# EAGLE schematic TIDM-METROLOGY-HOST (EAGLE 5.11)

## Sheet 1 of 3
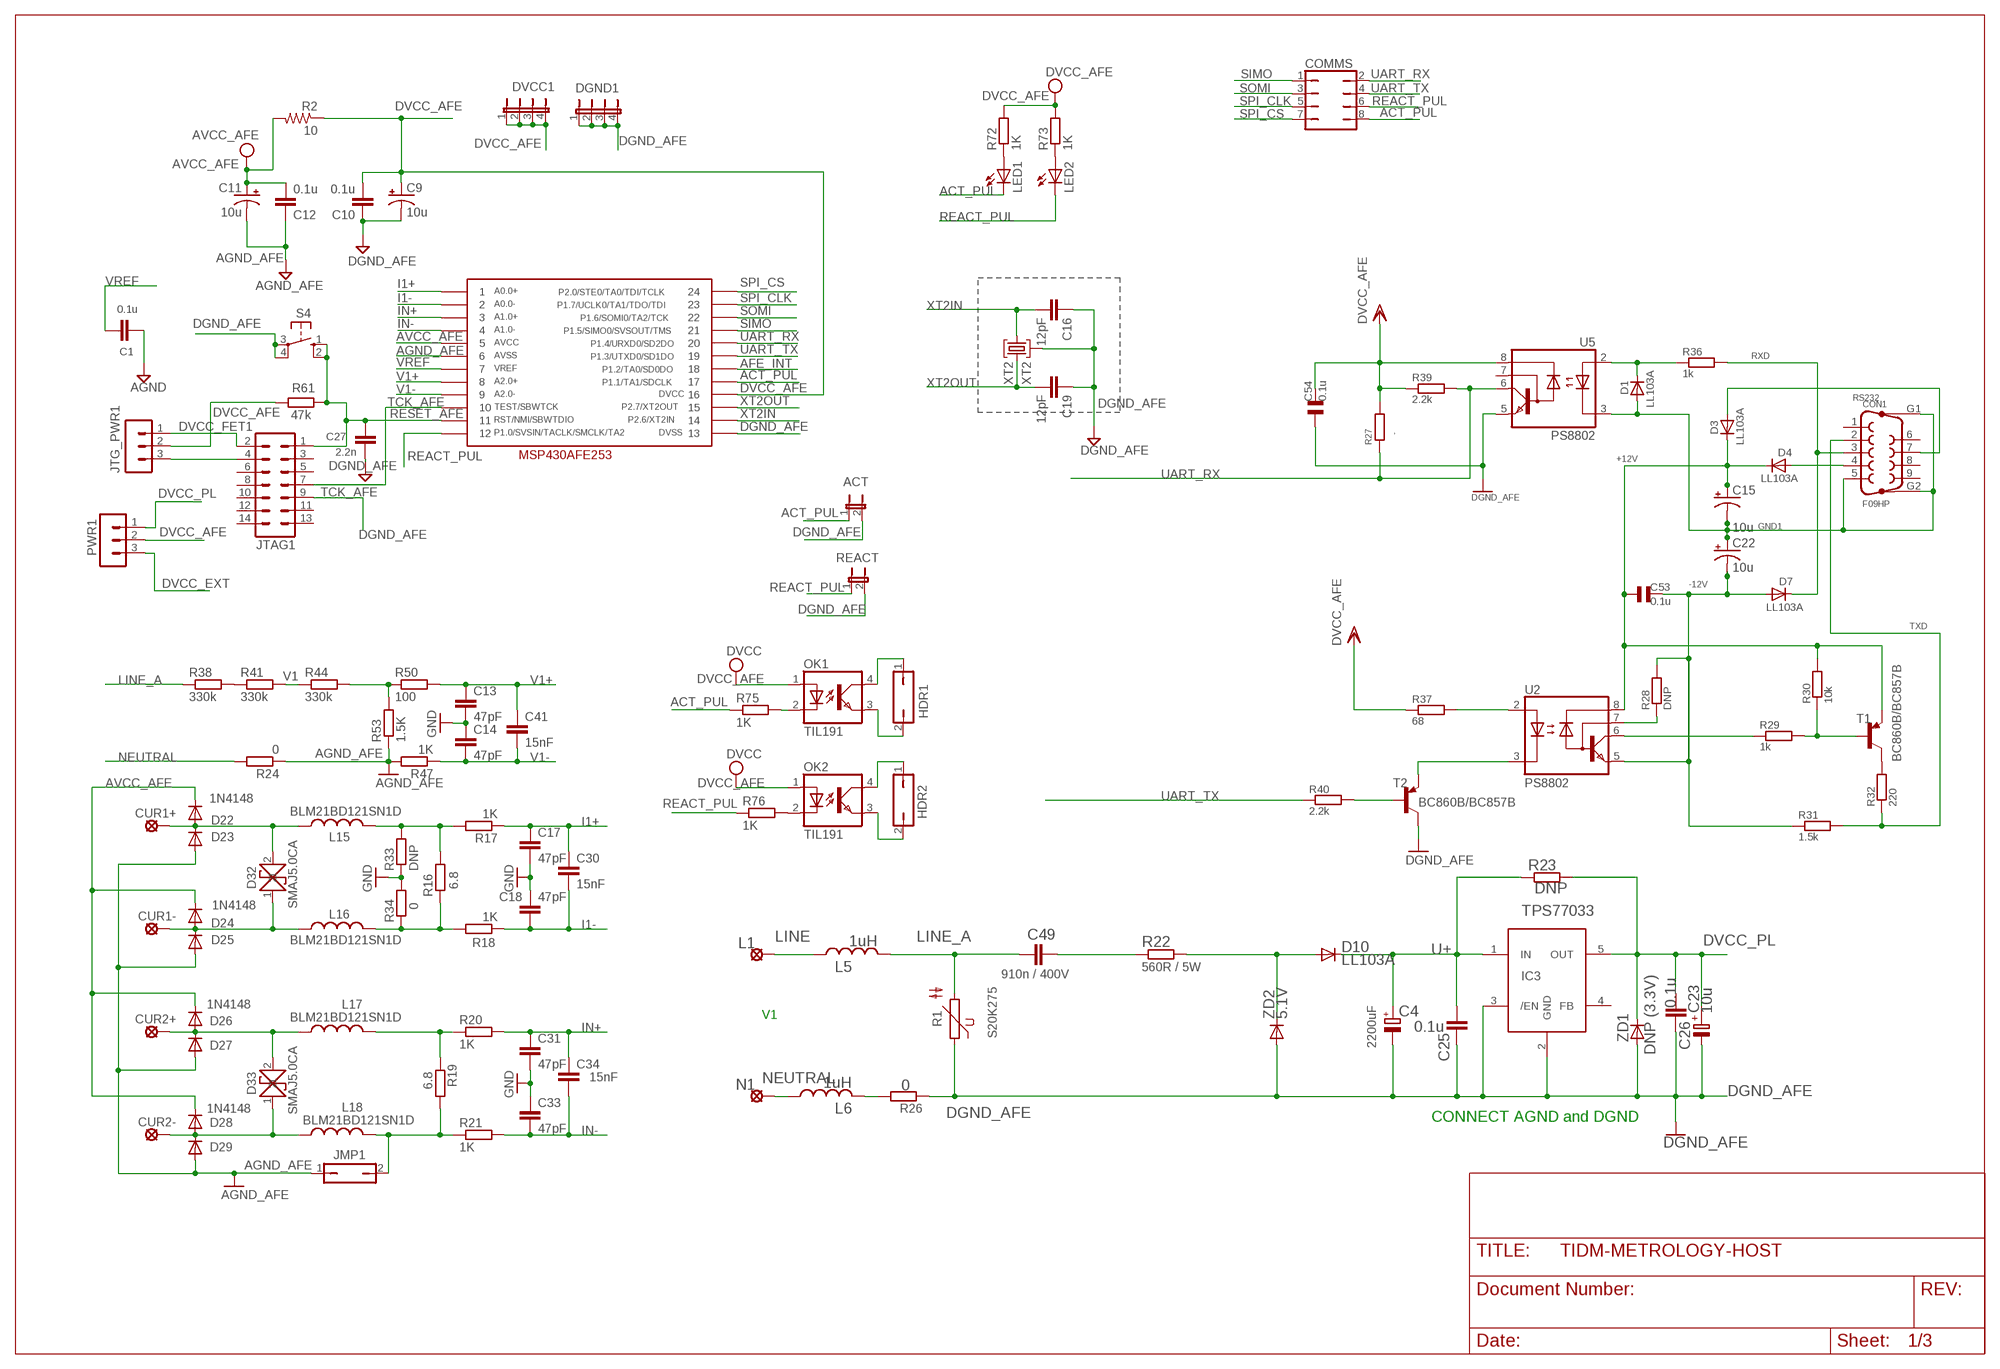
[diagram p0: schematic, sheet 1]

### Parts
ACT  JP1E  [JP1]
C1  0.1u  C-EUC0603  [C0603]
C4  2200uF  CPOL-EUE5-13  [E5-13]
C9  10u  CPOL-USCT3216  [CT3216]
C10  0.1u  C-EUC0603  [C0603]
C11  10u  CPOL-USCT3216  [CT3216]
C12  0.1u  C-EUC0603  [C0603]
C13  47pF  C-EUC0603  [C0603]
C14  47pF  C-EUC0603  [C0603]
C15  10u  CPOL-USCT3216  [CT3216]
C16  12pF  C-EUC0603  [C0603]
C17  47pF  C-EUC0603  [C0603]
C18  47pF  C-EUC0603  [C0603]
C19  12pF  C-EUC0603  [C0603]
C22  10u  CPOL-USCT3216  [CT3216]
C23  10u  ELKO_1210  [1210ELKO]
C25  0.1u  C-EUC0603  [C0603]
C26  0.1u  C-EUC0603  [C0603]
C27  2.2n  C-EUC0603  [C0603]
C30  15nF  C-EUC0603  [C0603]
C31  47pF  C-EUC0603  [C0603]
C33  47pF  C-EUC0603  [C0603]
C34  15nF  C-EUC0603  [C0603]
C41  15nF  C-EUC0603  [C0603]
C49  910n / 400V  C-EU225-062X268  [C225-062X268]
C53  0.1u  CSMD0805  [CSMD0805]
C54  0.1u  CSMD0805  [CSMD0805]
COMMS  JP4Q  [JP4Q]
CON1  F09HP  [F09HP]
CUR1+  LSP10  [LSP10]
CUR1-  LSP10  [LSP10]
CUR2+  LSP10  [LSP10]
CUR2-  LSP10  [LSP10]
D1  LL103A  D  [SOD-80]
D3  LL103A  D  [SOD-80]
D4  LL103A  D  [SOD-80]
D7  LL103A  D  [SOD-80]
D10  LL103A  D  [SOD-80]
D22  1N4148  1N4148SOD80C  [SOD80C]
D23  1N4148  1N4148SOD80C  [SOD80C]
D24  1N4148  1N4148SOD80C  [SOD80C]
D25  1N4148  1N4148SOD80C  [SOD80C]
D26  1N4148  1N4148SOD80C  [SOD80C]
D27  1N4148  1N4148SOD80C  [SOD80C]
D28  1N4148  1N4148SOD80C  [SOD80C]
D29  1N4148  1N4148SOD80C  [SOD80C]
D32  SMAJ5.0CA  SMAJ  [DO-214]
D33  SMAJ5.0CA  SMAJ  [DO-214]
DGND1  JP4E  [JP4]
DVCC1  JP4E  [JP4]
HDR1  JP1Q  [JP1]
HDR2  JP1Q  [JP1]
IC3  TPS77033  TPS77001  [SOT23/5]
JMP1  JP1Q  [JP1]
JTAG1  MA07-2MA07-2JTAG  [MA07-2JTAG]
JTG_PWR1  MA03-1MA03-1  [MA03-1]
L1  LSP10  [LSP10]
L5  1uH  L-US08050805  [0805@1]
L6  1uH  L-US08050805  [0805@1]
L15  BLM21BD121SN1D  L-USL2012C  [L2012C]
L16  BLM21BD121SN1D  L-USL2012C  [L2012C]
L17  BLM21BD121SN1D  L-USL2012C  [L2012C]
L18  BLM21BD121SN1D  L-USL2012C  [L2012C]
LED1  LED3MM  [LED3MM]
LED2  LED3MM  [LED3MM]
N1  LSP10  [LSP10]
OK1  TIL191  [DIL04]
OK2  TIL191  [DIL04]
PWR1  MA03-1MA03-1  [MA03-1]
R1  S20K275  [S20K275]
R2  10  R-US_R0603  [R0603]
R16  6.8  R-EU_R0603  [R0603]
R17  1K  R-EU_R0603  [R0603]
R18  1K  R-EU_R0603  [R0603]
R19  6.8  R-EU_R0603  [R0603]
R20  1K  R-EU_R0603  [R0603]
R21  1K  R-EU_R0603  [R0603]
R22  560R / 5W  R-EU_0817/7V  [P0817V@1]
R23  DNP  R_0805  [0805]
R24  0  R-EU_R0603  [R0603]
R26  0  R-EU_R0603  [R0603]
R27  -  0204/5  [0805]
R28  DNP  R_0805  [0805]
R29  1k  R_0805  [0805]
R30  10k  R_0805  [0805]
R31  1.5k  R_0805  [0805]
R32  220  R_0805  [0805]
R33  DNP  R-EU_R0603  [R0603]
R34  0  R-EU_R0603  [R0603]
R36  1k  R_0805  [0805]
R37  68  R_0805  [0805]
R38  330k  R-EU_R0603  [R0603]
R39  2.2k  R_0805  [0805]
R40  2.2k  R_0805  [0805]
R41  330k  R-EU_R0603  [R0603]
R44  330k  R-EU_R0603  [R0603]
R47  1K  R-EU_R0603  [R0603]
R50  100  R-EU_R0603  [R0603]
R53  1.5K  R-EU_R0603  [R0603]
R61  47k  R-EU_R0603  [R0603]
R72  1K  R-EU_R0603  [R0603]
R73  1K  R-EU_R0603  [R0603]
R75  1K  R-EU_R0603  [R0603]
R76  1K  R-EU_R0603  [R0603]
REACT  JP1E  [JP1]
S4  10-XX  [B3F-10XX]
T1  BC860B/BC857B  BC857ASMD  [SOT23-BEC]
T2  BC860B/BC857B  BC857ASMD  [SOT23-BEC]
U2  PS8802  PS8802SO08  [SO08]
U5  PS8802  PS8802SO08  [SO08]
U$1  MSP430AFE_24TSSOP  [MSP430AFE_24TSSOP]
XT2  XT2  X905  [X905]
ZD1  DNP (3.3V)  D  [SOD-80]
ZD2  5.1V  D  [SOD-80]

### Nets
+12V: C15.+ C53.1 D3.2(K) D4.2(K) R30.2 T1.E U2.8(VCC)
+12V1: CON1.7 D3.1(A)
+12V3: CON1.4 D4.1(A)
-12V: C22.- C53.2 D7.1(A) R28.2 R31.1 U2.5(GND)
ACT_PUL: ACT.1 COMMS.8 LED1.K(C) R75.1 U$1.P$17
AFE_INT: U$1.P$18 ; also sheet 2
AGND_AFE: C1.1 C11.- C12.1 C13.2 C14.1 C17.2 C18.1 C31.2 C33.1 D23.A D25.A D27.A D29.A JMP1.1 R24.1 R33.1 R34.2 R47.2 R53.1 U$1.P$6 ; supply symbol labelled GND, AGND
AVCC_AFE: C11.+ C12.2 D22.C D24.C D26.C D28.C R2.2 U$1.P$5
DGND_AFE: ACT.2 C4.- C9.- C10.1 C16.1 C19.1 C23.- C25.1 C26.1 C27.2 C54.1 DGND1.1 DGND1.2 DGND1.3 DGND1.4 IC3.2(GND) IC3.3(/EN) JTAG1.9 R1.1 R26.1 REACT.2 S4.3(P) S4.4(P1) T2.C U5.5(GND) U$1.P$13 XT2.2 ZD1.1(A) ZD2.1(A) ; also sheet 2
DVCC_AFE: C9.+ C10.2 C54.2 DVCC1.1 DVCC1.2 DVCC1.3 DVCC1.4 JTG_PWR1.2 OK1.1(A) OK2.1(A) PWR1.2 R2.1 R27.2 R37.1 R39.1 R61.1 R72.2 R73.2 U5.8(VCC) U$1.P$16 ; supply symbol labelled DVCC ; also sheet 2
DVCC_EXT: PWR1.3
DVCC_FET1: JTAG1.2 JTG_PWR1.1
DVCC_PL: C23.+ C26.2 IC3.5(OUT) PWR1.1 R23.2 ZD1.2(K)
GND1: C15.- C22.+ CON1.5 CON1.G1 CON1.G2 D1.1(A) U5.3(C)
I1+: C17.1 C30.1 R17.1 U$1.P$1
I1-: C18.2 C30.2 R18.1 U$1.P$2
IN+: C31.1 C34.1 R20.2 U$1.P$3
IN-: C33.2 C34.2 R21.2 U$1.P$4
LINE: L1.MP L5.1
LINE_A: C49.1 L5.2 R1.2 R38.1
N$1: L6.2 R26.2
N$2: D1.2(K) R36.1 U5.2(A)
N$3: R28.1 U2.7(VB)
N$4: R29.1 U2.6(VO)
N$5: R32.2 T1.C
N$8: R40.2 T2.B
N$19: CUR1+.MP D22.A D23.C D32.2 L15.1
N$20: CUR1-.MP D24.A D25.C D32.1 L16.1
N$21: CUR2+.MP D26.A D27.C D33.2 L17.1
N$22: CUR2-.MP D28.A D29.C D33.1 L18.1
N$24: JMP1.2 L18.2 R19.2 R21.1
N$26: C49.2 R22.1
N$27: L16.2 R16.1 R18.2 R34.1
N$29: D10.1(A) R22.2 ZD2.2(K)
N$30: R29.2 R30.1 T1.B
N$31: L17.2 R19.1 R20.1
N$32: R44.2 R50.1 R53.2
N$39: R38.2 R41.1
N$42: L15.2 R16.2 R17.2 R33.2
N$49: R37.2 U2.2(A)
N$104: LED1.A R72.1
N$105: LED2.A R73.1
N$109: HDR1.1 OK1.4(COL)
N$113: OK2.2(C) R76.2
N$114: OK1.2(C) R75.2
N$117: HDR1.2 OK1.3(EMIT)
N$118: HDR2.1 OK2.4(COL)
N$119: HDR2.2 OK2.3(EMIT)
N$130: JTAG1.4 JTG_PWR1.3
N$455: T2.E U2.3(C)
NEUTRAL: L6.1 N1.MP R24.2
REACT_PUL: COMMS.6 LED2.K(C) R76.1 REACT.1 U$1.P$12
RESET_AFE: C27.1 JTAG1.1 R61.2 S4.1(S) S4.2(S1) U$1.P$11
RXD: CON1.3 D7.2(K) R36.2
SIMO: COMMS.1 U$1.P$21 ; also sheet 2
SOMI: COMMS.3 U$1.P$22 ; also sheet 2
SPI_CLK: COMMS.5 U$1.P$23 ; also sheet 2
SPI_CS: COMMS.7 U$1.P$24 ; also sheet 2
TCK_AFE: JTAG1.7 U$1.P$10
TXD: CON1.2 R31.2 R32.1
U+: C4.+ C25.2 D10.2(K) IC3.1(IN) R23.1
UART_RX: COMMS.2 R27.1 R39.2 U5.6(VO) U$1.P$20
UART_TX: COMMS.4 R40.1 U$1.P$19
V1: R41.2 R44.1
V1+: C13.1 C41.1 R50.2 U$1.P$8
V1-: C14.2 C41.2 R47.1 U$1.P$9
VREF: C1.2 U$1.P$7
XT2IN: C16.2 U$1.P$14 XT2.1
XT2OUT: C19.2 U$1.P$15 XT2.3
Unconnected: CON1.1 CON1.6 CON1.8 CON1.9 IC3.4(FB) JTAG1.3 JTAG1.5 JTAG1.6 JTAG1.8 JTAG1.10 JTAG1.11 JTAG1.12 JTAG1.13 JTAG1.14 U5.7(VB)

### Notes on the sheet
- RS232
- V1
- CONNECT AGND and DGND

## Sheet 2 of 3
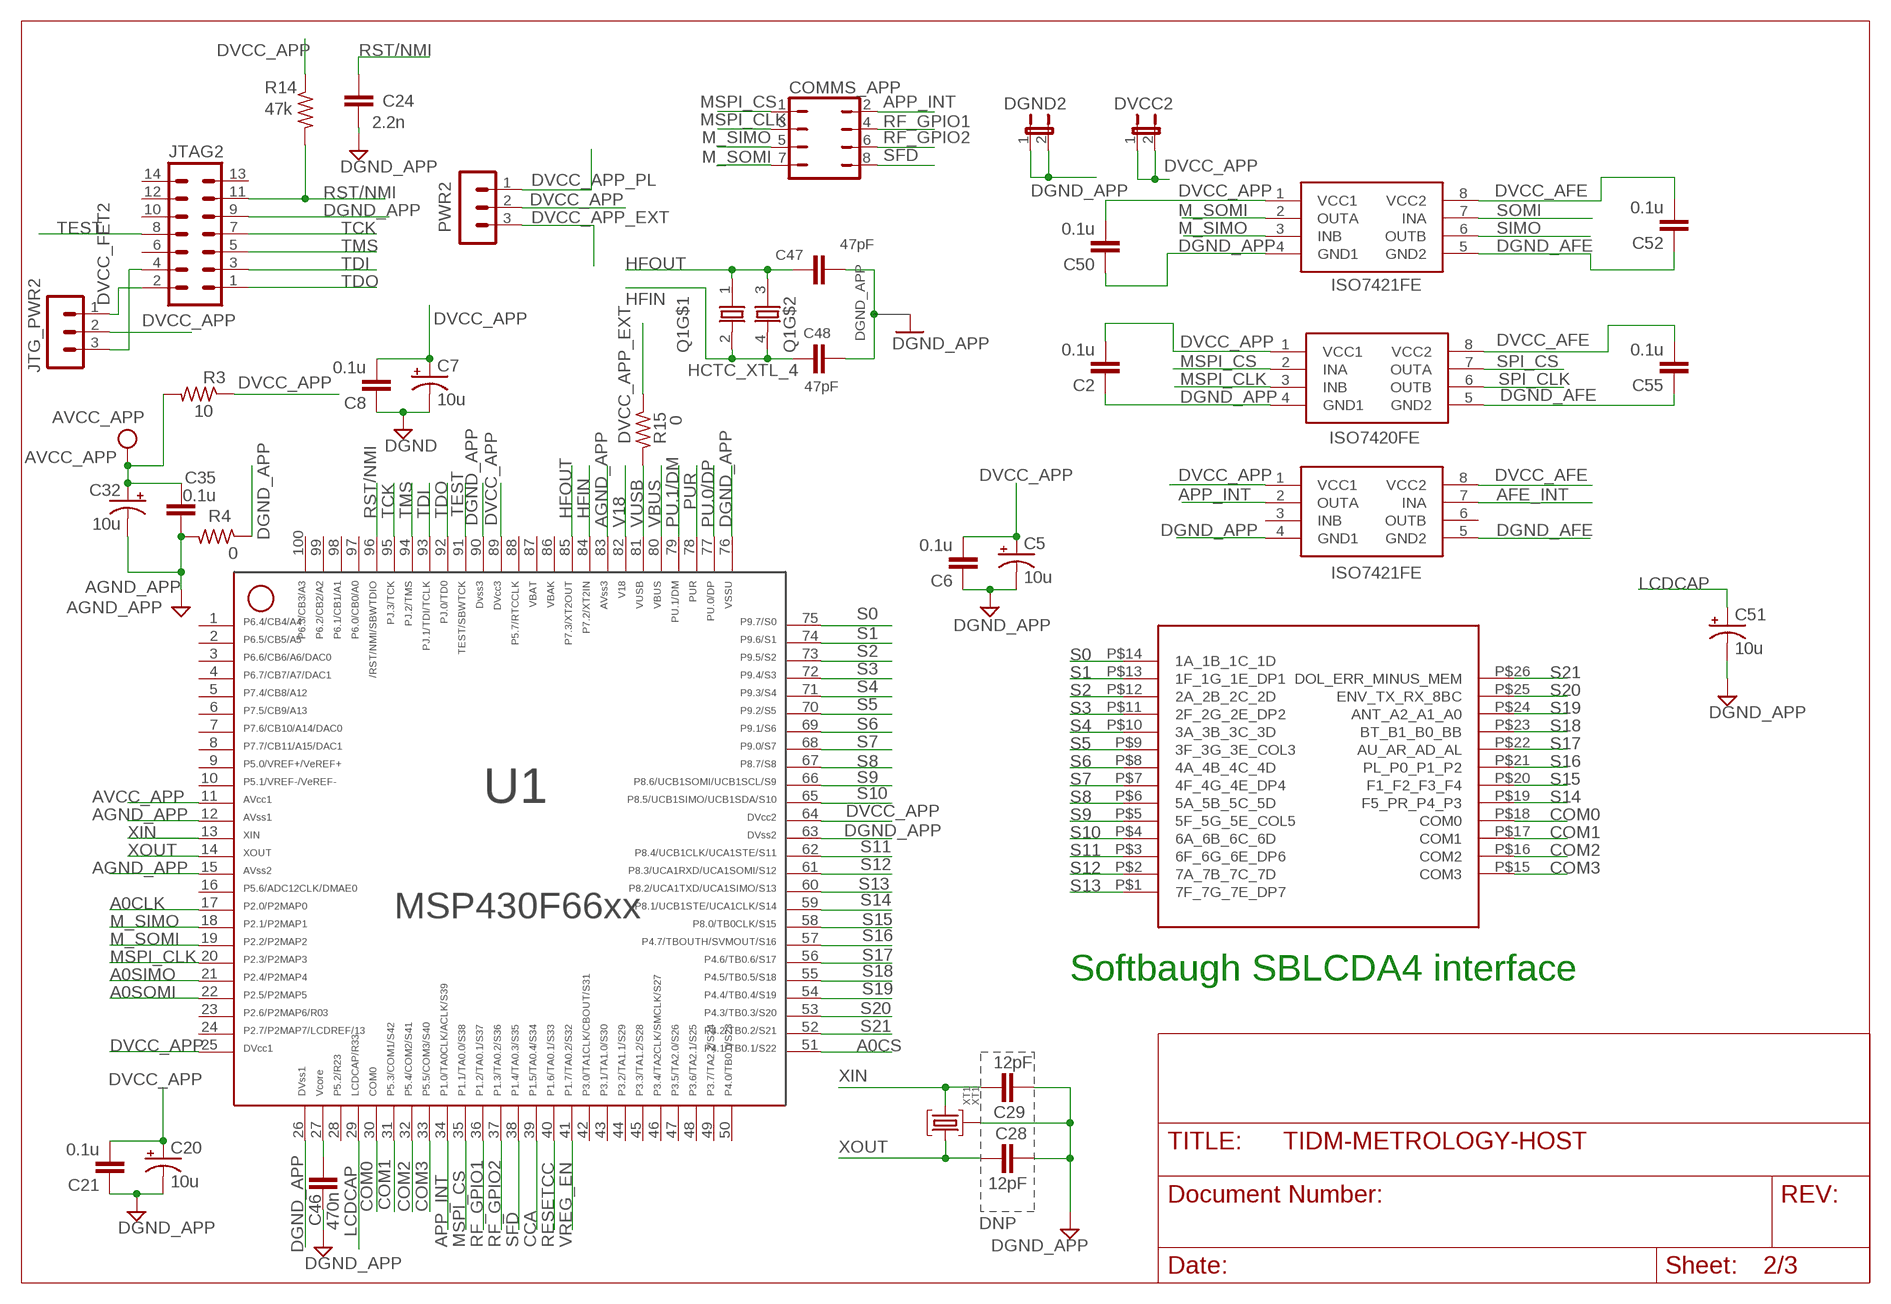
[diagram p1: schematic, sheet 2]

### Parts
C2  0.1u  C-EUC0603  [C0603]
C5  10u  CPOL-USCT3216  [CT3216]
C6  0.1u  C-EUC0603  [C0603]
C7  10u  CPOL-USCT3216  [CT3216]
C8  0.1u  C-EUC0603  [C0603]
C20  10u  CPOL-USCT3216  [CT3216]
C21  0.1u  C-EUC0603  [C0603]
C24  2.2n  C-EUC0603  [C0603]
C28  12pF  C-EUC0603  [C0603]
C29  12pF  C-EUC0603  [C0603]
C32  10u  CPOL-USCT3216  [CT3216]
C35  0.1u  C-EUC0603  [C0603]
C46  470n  C-EUC0603  [C0603]
C47  47pF  C-EUC0603  [C0603]
C48  47pF  C-EUC0603  [C0603]
C50  0.1u  C-EUC0603  [C0603]
C51  10u  CPOL-USCT3216  [CT3216]
C52  0.1u  C-EUC0603  [C0603]
C55  0.1u  C-EUC0603  [C0603]
COMMS_APP  JP4Q  [JP4Q]
DGND2  JP1E  [JP1]
DVCC2  JP1E  [JP1]
ISO1  ISO7420FE  ISO7220  [SO-08]
ISO2  ISO7421FE  ISO7221  [SO-08]
ISO3  ISO7421FE  ISO7221  [SO-08]
JTAG2  ML14  [ML14]
JTG_PWR2  MA03-1MA03-1  [MA03-1]
LCD1  SBLCDA4  [SBLCDA4]
PWR2  MA03-1MA03-1  [MA03-1]
Q1  HCTC_XTL_4  [HCTC]
R3  10  R-US_R0603  [R0603]
R4  0  R-US_R0603  [R0603]
R14  47k  R-US_R0603  [R0603]
R15  0  R-US_R0603  [R0603]
U1  F66XX---PZ100  [PZ100]
XT1  XT1  CM200T  [CM200T]

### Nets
A0CLK: U1.17 ; also sheet 3
A0CS: U1.51 ; also sheet 3
A0SIMO: U1.21 ; also sheet 3
A0SOMI: U1.22 ; also sheet 3
AFE_INT: ISO3.7(INA) ; also sheet 1
AGND_APP: C32.- C35.1 R4.2 U1.12 U1.15 U1.83
APP_INT: COMMS_APP.2 ISO3.2(OUTA) U1.34
AVCC_APP: C32.+ C35.2 R3.2 U1.11
CCA: U1.39 ; also sheet 3
COM0: LCD1.P$18(COM0) U1.30
COM1: LCD1.P$17(COM1) U1.31
COM2: LCD1.P$16(COM2) U1.32
COM3: LCD1.P$15(COM3) U1.33
DGND_AFE: C52.1 C55.1 ISO1.5(GND2) ISO2.5(GND2) ISO3.5(GND2) ; also sheet 1
DGND_APP: C2.1 C5.- C6.1 C7.- C8.1 C20.- C21.1 C24.1 C28.1 C29.2 C46.2 C47.2 C48.2 C50.1 C51.- DGND2.1 DGND2.2 ISO1.4(GND1) ISO2.4(GND1) ISO3.4(GND1) JTAG2.9 R4.1 U1.26 U1.63 U1.76 U1.90 XT1.P3 ; supply symbol labelled DGND ; also sheet 3
DVCC_AFE: C52.2 C55.2 ISO1.8(VCC2) ISO2.8(VCC2) ISO3.8(VCC2) ; also sheet 1
DVCC_APP: C2.2 C5.+ C6.2 C7.+ C8.2 C20.+ C21.2 C50.2 DVCC2.1 DVCC2.2 ISO1.1(VCC1) ISO2.1(VCC1) ISO3.1(VCC1) JTG_PWR2.2 PWR2.2 R3.1 R14.1 U1.25 U1.64 U1.89 ; also sheet 3
DVCC_APP_EXT: PWR2.3 R15.1
DVCC_APP_PL: PWR2.1 ; also sheet 3
DVCC_FET2: JTAG2.2 JTG_PWR2.1
HFIN: C48.1 Q1.2 Q1.4 U1.84
HFOUT: C47.1 Q1.1 Q1.3 U1.85
LCDCAP: C51.+ U1.29
M_SIMO: COMMS_APP.5 ISO2.3(INB) U1.18
M_SOMI: COMMS_APP.7 ISO2.2(OUTA) U1.19
MSPI_CLK: COMMS_APP.3 ISO1.3(INB) U1.20
MSPI_CS: COMMS_APP.1 ISO1.2(INA) U1.35
N$9: JTAG2.4 JTG_PWR2.3
N$11: C46.1 U1.27
PU.0/DP: U1.77 ; also sheet 3
PU.1/DM: U1.79 ; also sheet 3
PUR: U1.78 ; also sheet 3
RESETCC: U1.40 ; also sheet 3
RF_GPIO1: COMMS_APP.4 U1.36 ; also sheet 3
RF_GPIO2: COMMS_APP.6 U1.37 ; also sheet 3
RST/NMI: C24.2 JTAG2.11 R14.2 U1.96
S0: LCD1.P$14(1A_1B_1C_1D) U1.75
S1: LCD1.P$13(1F_1G_1E_DP1) U1.74
S2: LCD1.P$12(2A_2B_2C_2D) U1.73
S3: LCD1.P$11(2F_2G_2E_DP2) U1.72
S4: LCD1.P$10(3A_3B_3C_3D) U1.71
S5: LCD1.P$9(3F_3G_3E_COL3) U1.70
S6: LCD1.P$8(4A_4B_4C_4D) U1.69
S7: LCD1.P$7(4F_4G_4E_DP4) U1.68
S8: LCD1.P$6(5A_5B_5C_5D) U1.67
S9: LCD1.P$5(5F_5G_5E_COL5) U1.66
S10: LCD1.P$4(6A_6B_6C_6D) U1.65
S11: LCD1.P$3(6F_6G_6E_DP6) U1.62
S12: LCD1.P$2(7A_7B_7C_7D) U1.61
S13: LCD1.P$1(7F_7G_7E_DP7) U1.60
S14: LCD1.P$19(F5_PR_P4_P3) U1.59
S15: LCD1.P$20(F1_F2_F3_F4) U1.58
S16: LCD1.P$21(PL_P0_P1_P2) U1.57
S17: LCD1.P$22(AU_AR_AD_AL) U1.56
S18: LCD1.P$23(BT_B1_B0_BB) U1.55
S19: LCD1.P$24(ANT_A2_A1_A0) U1.54
S20: LCD1.P$25(ENV_TX_RX_8BC) U1.53
S21: LCD1.P$26(DOL_ERR_MINUS_MEM) U1.52
SFD: COMMS_APP.8 U1.38 ; also sheet 3
SIMO: ISO2.6(OUTB) ; also sheet 1
SOMI: ISO2.7(INA) ; also sheet 1
SPI_CLK: ISO1.6(OUTB) ; also sheet 1
SPI_CS: ISO1.7(OUTA) ; also sheet 1
TCK: JTAG2.7 U1.95
TDI: JTAG2.3 U1.93
TDO: JTAG2.1 U1.92
TEST: JTAG2.8 U1.91
TMS: JTAG2.5 U1.94
V18: U1.82
VBUS: U1.80 ; also sheet 3
VREG_EN: U1.41 ; also sheet 3
VUSB: R15.2 U1.81
XIN: C29.1 U1.13 XT1.P2
XOUT: C28.2 U1.14 XT1.P1
Unconnected: ISO3.3(INB) ISO3.6(OUTB) JTAG2.6 JTAG2.10 JTAG2.12 JTAG2.13 JTAG2.14 U1.1 U1.2 U1.3 U1.4 U1.5 U1.6 U1.7 U1.8 U1.9 U1.10 U1.16 U1.23 U1.24 U1.28 U1.42 U1.43 U1.44 U1.45 U1.46 U1.47 U1.48 U1.49 U1.50 U1.86 U1.87 U1.88 U1.97 U1.98 U1.99 U1.100

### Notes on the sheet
- ISO7421FE
- ISO7420FE
- ISO7421FE
- Softbaugh SBLCDA4 interface
- DNP

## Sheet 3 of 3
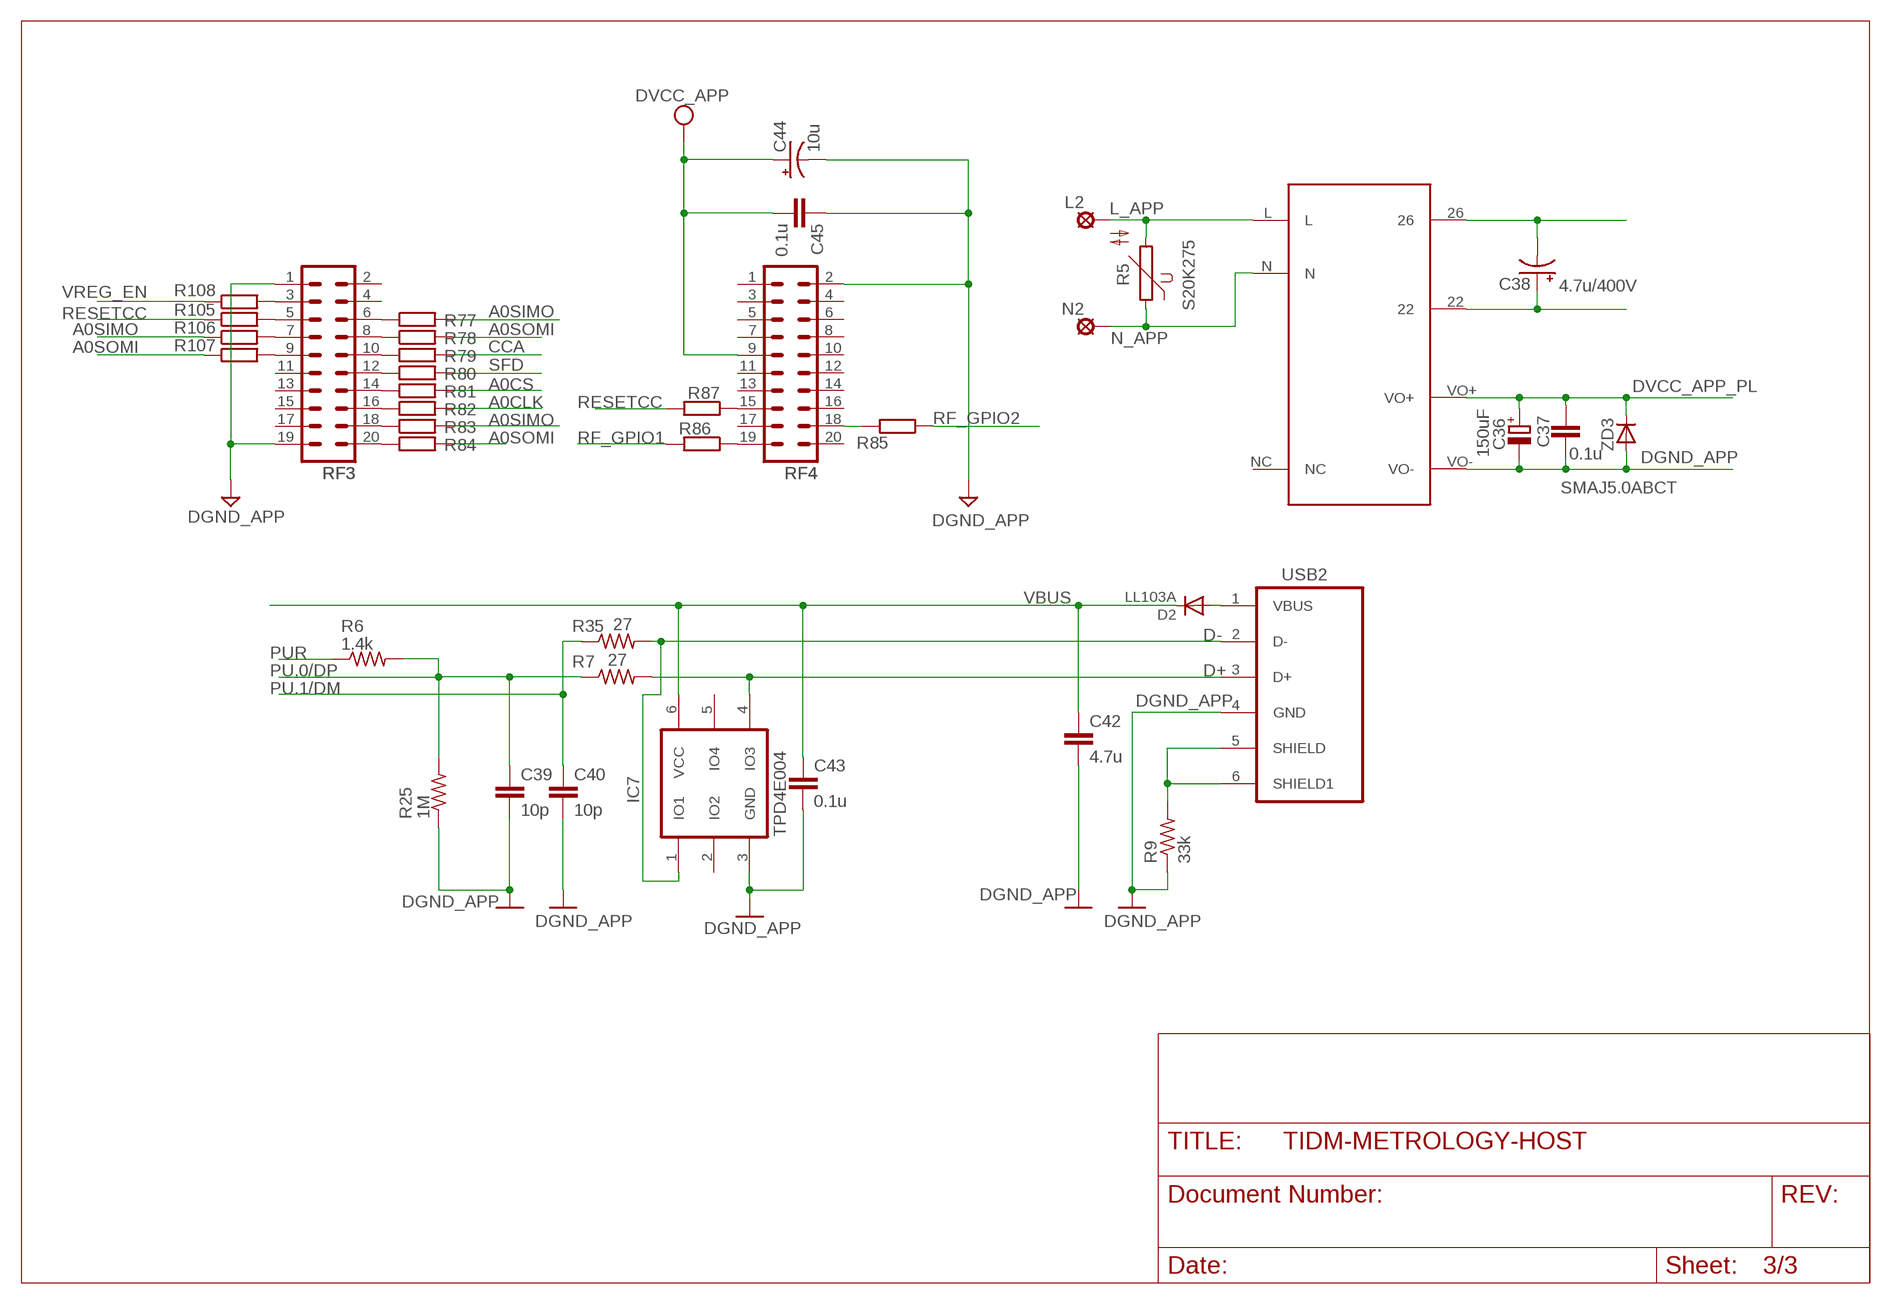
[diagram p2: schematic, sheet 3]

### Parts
C36  150uF  CPOL-EUE2-5  [E2-5]
C37  0.1u  C-EUC0603  [C0603]
C38  4.7u/400V  CPOL-USE5-10.5  [E5-10,5]
C39  10p  C-EUC0603  [C0603]
C40  10p  C-EUC0603  [C0603]
C42  4.7u  C-EUC0603  [C0603]
C43  0.1u  C-EUC0603  [C0603]
C44  10u  CPOL-USCT3216  [CT3216]
C45  0.1u  C-EUC0603  [C0603]
D2  LL103A  D  [SOD-80]
IC7  TPD4E004  [DRY6]
L2  LSP10  [LSP10]
N2  LSP10  [LSP10]
R5  S20K275  [S20K275]
R6  1.4k  R-US_R0603  [R0603]
R7  27  R-US_R0603  [R0603]
R9  33k  R-US_R0603  [R0603]
R25  1M  R-US_R0603  [R0603]
R35  27  R-US_R0603  [R0603]
R77  0  R-EU_R0603  [R0603@1]
R78  0  R-EU_R0603  [R0603@1]
R79  0  R-EU_R0603  [R0603@1]
R80  0  R-EU_R0603  [R0603@1]
R81  0  R-EU_R0603  [R0603@1]
R82  0  R-EU_R0603  [R0603@1]
R83  0  R-EU_R0603  [R0603@1]
R84  0  R-EU_R0603  [R0603@1]
R85  0  R-EU_R0603  [R0603@1]
R86  0  R-EU_R0603  [R0603@1]
R87  0  R-EU_R0603  [R0603@1]
R105  0  R-EU_R0603  [R0603@1]
R106  0  R-EU_R0603  [R0603@1]
R107  0  R-EU_R0603  [R0603@1]
R108  0  R-EU_R0603  [R0603@1]
RF3  TFM-110-02-SM-D-A-K  [TFM-110-02-SM-D-A-K]
RF4  TFM-110-02-SM-D-A-K  [TFM-110-02-SM-D-A-K]
U$2  CUI_XR  [CUI_XR]
USB2  USB_RECEPTACLE  [USB_BUCHSE]
ZD3  SMAJ5.0ABCT  DIODE-DO214AC  [DO214AC]

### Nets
A0CLK: R82.2 ; also sheet 2
A0CS: R81.2 ; also sheet 2
A0SIMO: R77.2 R83.2 R106.1 ; also sheet 2
A0SOMI: R78.2 R84.2 R107.1 ; also sheet 2
CCA: R79.2 ; also sheet 2
D+: IC7.4(IO3) R7.2 USB2.3(D+)
D-: IC7.1(IO1) R35.2 USB2.2(D-)
DGND_APP: C36.- C37.2 C39.2 C40.2 C42.2 C43.2 C44.- C45.1 IC7.3(GND) R9.1 R25.1 RF3.1 RF3.19 RF4.2 U$2.VO- USB2.4(GND) ZD3.A ; also sheet 2
DVCC_APP: C44.+ C45.2 RF4.9 ; also sheet 2
DVCC_APP_PL: C36.+ C37.1 U$2.VO+ ZD3.C ; also sheet 2
L_APP: L2.MP R5.2 U$2.L
N$6: R107.2 RF3.9
N$7: R87.1 RF4.15
N$10: R9.2 USB2.5(SHIELD) USB2.6(SHIELD1)
N$12: C38.- U$2.26
N$13: C38.+ U$2.22
N$51: D2.1(A) USB2.1(VBUS)
N$52: R108.2 RF3.3
N$56: R77.1 RF3.6
N$57: R78.1 RF3.8
N$58: R79.1 RF3.10
N$60: R80.1 RF3.12
N$61: R81.1 RF3.14
N$62: R82.1 RF3.16
N$63: R83.1 RF3.18
N$64: R84.1 RF3.20
N$65: R85.2 RF4.18
N$108: R86.1 RF4.19
N$110: R105.2 RF3.5
N$111: R106.2 RF3.7
N_APP: N2.MP R5.1 U$2.N
PU.0/DP: C39.1 R6.2 R7.1 R25.2 ; also sheet 2
PU.1/DM: C40.1 R35.1 ; also sheet 2
PUR: R6.1 ; also sheet 2
RESETCC: R87.2 R105.1 ; also sheet 2
RF_GPIO1: R86.2 ; also sheet 2
RF_GPIO2: R85.1 ; also sheet 2
SFD: R80.2 ; also sheet 2
VBUS: C42.1 C43.1 D2.2(K) IC7.6(VCC) ; also sheet 2
VREG_EN: R108.1 ; also sheet 2
Unconnected: IC7.2(IO2) RF3.2 RF3.4 RF3.11 RF3.13 RF3.15 RF3.17 RF4.1 RF4.3 RF4.4 RF4.5 RF4.6 RF4.7 RF4.8 RF4.10 RF4.11 RF4.12 RF4.13 RF4.14 RF4.16 RF4.17 RF4.20 U$2.NC

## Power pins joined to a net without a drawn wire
IO4: IC7.5(IO4)

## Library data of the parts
ACT DGND2 DVCC2 REACT = jumper:JP1E: JUMPER
C1 C2 C6 C8 C10 C12-C14 C16 C19 C21 C24-C29 C35 C37 C39-C43 C45-C48 C50 C52 C55 = resistor:C-EU: CAPACITOR, European symbol
C4 = ElecMeter:CPOL-EU: POLARIZED CAPACITOR, European symbol
C5 C7 C9 C11 C15 C20 C22 C32 C38 C44 C51 = rcl:CPOL-US: POLARIZED CAPACITOR, American symbol
C17 C18 C30 C31 C33 C34 = ElecMeter:C-EU: CAPACITOR, European symbol
C23 = SMD:ELKO_1210
C36 = rcl:CPOL-EU: POLARIZED CAPACITOR, European symbol
C49 = rcl:C-EU: CAPACITOR, European symbol
C53 C54 = CAP:CSMD0805
COMMS COMMS_APP = jumper:JP4Q: JUMPER
CON1 = SUBD-A:F09HP
CUR1+ CUR1- CUR2+ CUR2- L1 L2 N1 N2 = ElecMeter:LSP10: SOLDER PAD
D1-D4 D7 D10 ZD1 ZD2 = SMD:D
D22-D29 = ElecMeter:1N4148: DIODE
D32 D33 = CON1:SMAJ
DGND1 DVCC1 = jumper:JP4E: JUMPER
HDR1 HDR2 JMP1 = ElecMeter:JP1Q: JUMPER
IC3 = flash-evk:TPS77001
IC7 = gangprog:TPD4E004
ISO1 = texas:ISO7220
ISO2 ISO3 = texas:ISO7221
JTAG1 = ElecMeter:MA07-2: PIN HEADER
JTAG2 = CON-ML:ML14
JTG_PWR1 JTG_PWR2 PWR1 PWR2 = ElecMeter:MA03-1: PIN HEADER
L5 L6 = SMD:L-US0805
L15-L18 = ElecMeter:L-US: INDUCTOR, American symbol
LCD1 = Display-SoftBaugh2:SBLCDA4
LED1 LED2 = ElecMeter:LED: LED
OK1 OK2 = ElecMeter:TIL191: TEXAS INSTRUMENTS OPTO COUPLER
Q1 = scrystal:HCTC_XTL_4
R1 R5 = varistor:S20K275: VARISTOR
R2-R4 R14 R15 = resistor:R-US_: RESISTOR, American symbol
R6 R7 R9 R25 R35 = rcl:R-US_: RESISTOR, American symbol
R16-R21 R24 R26 R33 R34 R38 R41 R44 R47 R50 R53 R61 R72 R73 R75 R76 = ElecMeter:R-EU_: RESISTOR, European symbol
R22 R77-R87 R105-R108 = rcl:R-EU_: RESISTOR, European symbol
R23 R28-R32 R36 R37 R39 R40 = SMD:R_0805
R27 = R:0204/5
RF3 RF4 = _MSP430:TFM-110-02-SM-D-A-K
S4 = ElecMeter:10-XX: OMRON SWITCH
T1 T2 = transistor-pnp:BC857*: PNP Transistror
U1 = TI_MSP430_v16_intern:F66XX---PZ100: ***MSP430F66XX***PZ64 Rev 1.0 *** 06/2010
U2 U5 = FE449x EVM:PS8802: MOTOROLA OPTO COUPLER
U$1 = TI_MSP430_v15:MSP430AFE_24TSSOP
U$2 = TI_MSP430_v16_intern:CUI_XR
USB2 = susbfet:USB_RECEPTACLE: Lumberg: USB-Receptacle "B", 2413
XT1 = F20xx PIR Demo & Eval:CM200T
XT2 = ATC2004 Lab HW:X905: CRYSTAL
ZD3 = diode:DIODE-: DIODE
